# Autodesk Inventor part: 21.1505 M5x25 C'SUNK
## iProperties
Created: 2006-12
Part Number: 21.1505 M5x25 C'SUNK
Material: Steel, Mild
Description: Hexagon socket countersunk head cap screws
Document SubType Name: Modeling
Standard: DIN 7991
Designer: Andy Moles
Standards Organization: DIN
Language: en-US
Size Designation: M5x25
Categories: <MemberInstance Version="R10.0.0"><Categories><Category DisplayName="Fasteners" InternalName="e4da775c-781d-43d5-af7c-5136215cf5a6" Mnemonic="FSTN"><Category Di
Density: 7.86 g/cm^3
Author: Andy Moles
Revision Number: 1
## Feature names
1. Revolution1
2. Extrusion1
3. Fillet1
4. Chamfer1
